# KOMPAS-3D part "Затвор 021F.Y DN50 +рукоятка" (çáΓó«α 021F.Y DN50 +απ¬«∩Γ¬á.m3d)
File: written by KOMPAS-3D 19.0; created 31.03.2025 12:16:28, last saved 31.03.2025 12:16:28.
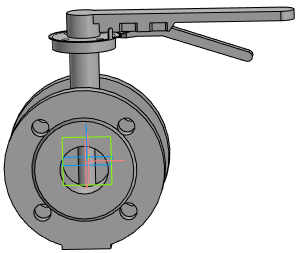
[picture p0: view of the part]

Document properties: Автор: Евгений; Полное имя файла: Затвор 021F.Y DN50 +рукоятка.a3d

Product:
- Part/product: Затвор 021F.Y DN50 +рукоятка
    Масса: 8.98489

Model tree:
1. Операция без истории:1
